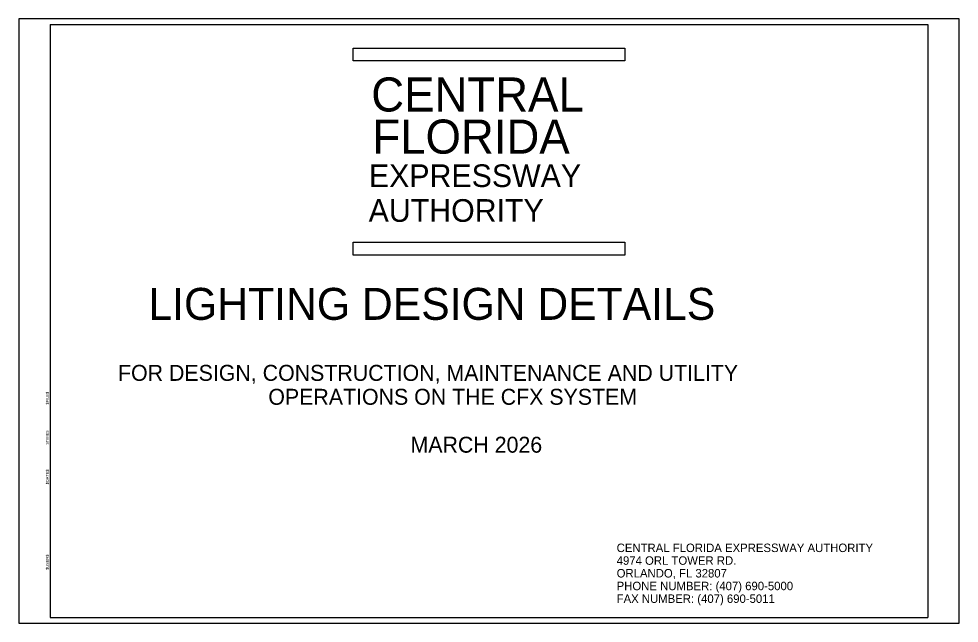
# Model space of a CAD drawing. Extents: x 1888.7 to 1905.2, y -90 to -79.4.
import ezdxf

# ---------------------------------------------------------------- set-up
doc = ezdxf.new("R2010")
doc.units = 0
for name, color, linetype in [('PlotBorder_dp', 7, 'Continuous'), ('SheetBorder_dp', 7, 'Continuous'), ('SignPanel', 7, 'Continuous'), ('TextLabel', 7, 'Continuous'), ('TextMisc', 7, 'Continuous'), ('TextStructures', 7, 'Continuous')]:
    doc.layers.add(name, color=color, linetype=linetype)

msp = doc.modelspace()

# ---------------------------------------------------------------- linework, layer by layer
at = {"layer": 'PlotBorder_dp'}
msp.add_lwpolyline([(1888.731, -90), (1905.231, -90), (1905.231, -79.4), (1888.731, -79.4)], close=True, dxfattribs=at)
at = {"layer": 'SheetBorder_dp'}
for p, q in [((1889.281, -79.5), (1889.281, -89.9)), ((1889.281, -79.5), (1904.681, -79.5)), ((1904.681, -79.5), (1904.681, -89.9)), ((1889.281, -89.9), (1904.681, -89.9))]:
    msp.add_line(p, q, dxfattribs=at)
at = {"layer": 'SignPanel'}
for points in [[(1894.598, -79.914), (1899.364, -79.914), (1899.364, -80.137), (1894.598, -80.137)], [(1894.598, -83.32), (1899.364, -83.32), (1899.364, -83.543), (1894.598, -83.543)]]:
    msp.add_lwpolyline(points, close=True, dxfattribs=at)

# ---------------------------------------------------------------- texts
for s, height, p in [('CENTRAL', 0.5974, (1894.915, -81.026)), ('FLORIDA', 0.5974, (1894.935, -81.765)), ('EXPRESSWAY', 0.3976, (1894.874, -82.351)), ('AUTHORITY', 0.3976, (1894.869, -82.961))]:
    msp.add_text(s, height=height, dxfattribs=at).set_placement(p)
at = {"layer": 'TextLabel'}
msp.add_text('LIGHTING DESIGN DETAILS', height=0.56, dxfattribs=at).set_placement((1891.006, -84.68))
at = {"layer": 'TextMisc'}
for s, p in [('$FILE$', (1889.256, -86.165)), ('$TIME$', (1889.256, -86.865)), ('$DATE$', (1889.256, -87.565)), ('$USER$', (1889.256, -89.065))]:
    msp.add_text(s, height=0.05, rotation=90, dxfattribs=at).set_placement(p)
at = {"layer": 'TextStructures'}
for s, height, p in [('FOR DESIGN, CONSTRUCTION, MAINTENANCE AND UTILITY', 0.28, (1890.472, -85.75)), ('OPERATIONS ON THE CFX SYSTEM', 0.28, (1893.109, -86.17)), ('MARCH 2026', 0.28, (1895.604, -87.01)), ('CENTRAL FLORIDA EXPRESSWAY AUTHORITY', 0.14875, (1899.221, -88.753)), ('4974 ORL TOWER RD.', 0.14875, (1899.221, -88.976)), ('ORLANDO, FL 32807', 0.14875, (1899.221, -89.199)), ('PHONE NUMBER: (407) 690-5000', 0.14875, (1899.221, -89.422)), ('FAX NUMBER: (407) 690-5011', 0.14875, (1899.221, -89.645))]:
    msp.add_text(s, height=height, dxfattribs=at).set_placement(p)

doc.saveas('drawing.dxf')
